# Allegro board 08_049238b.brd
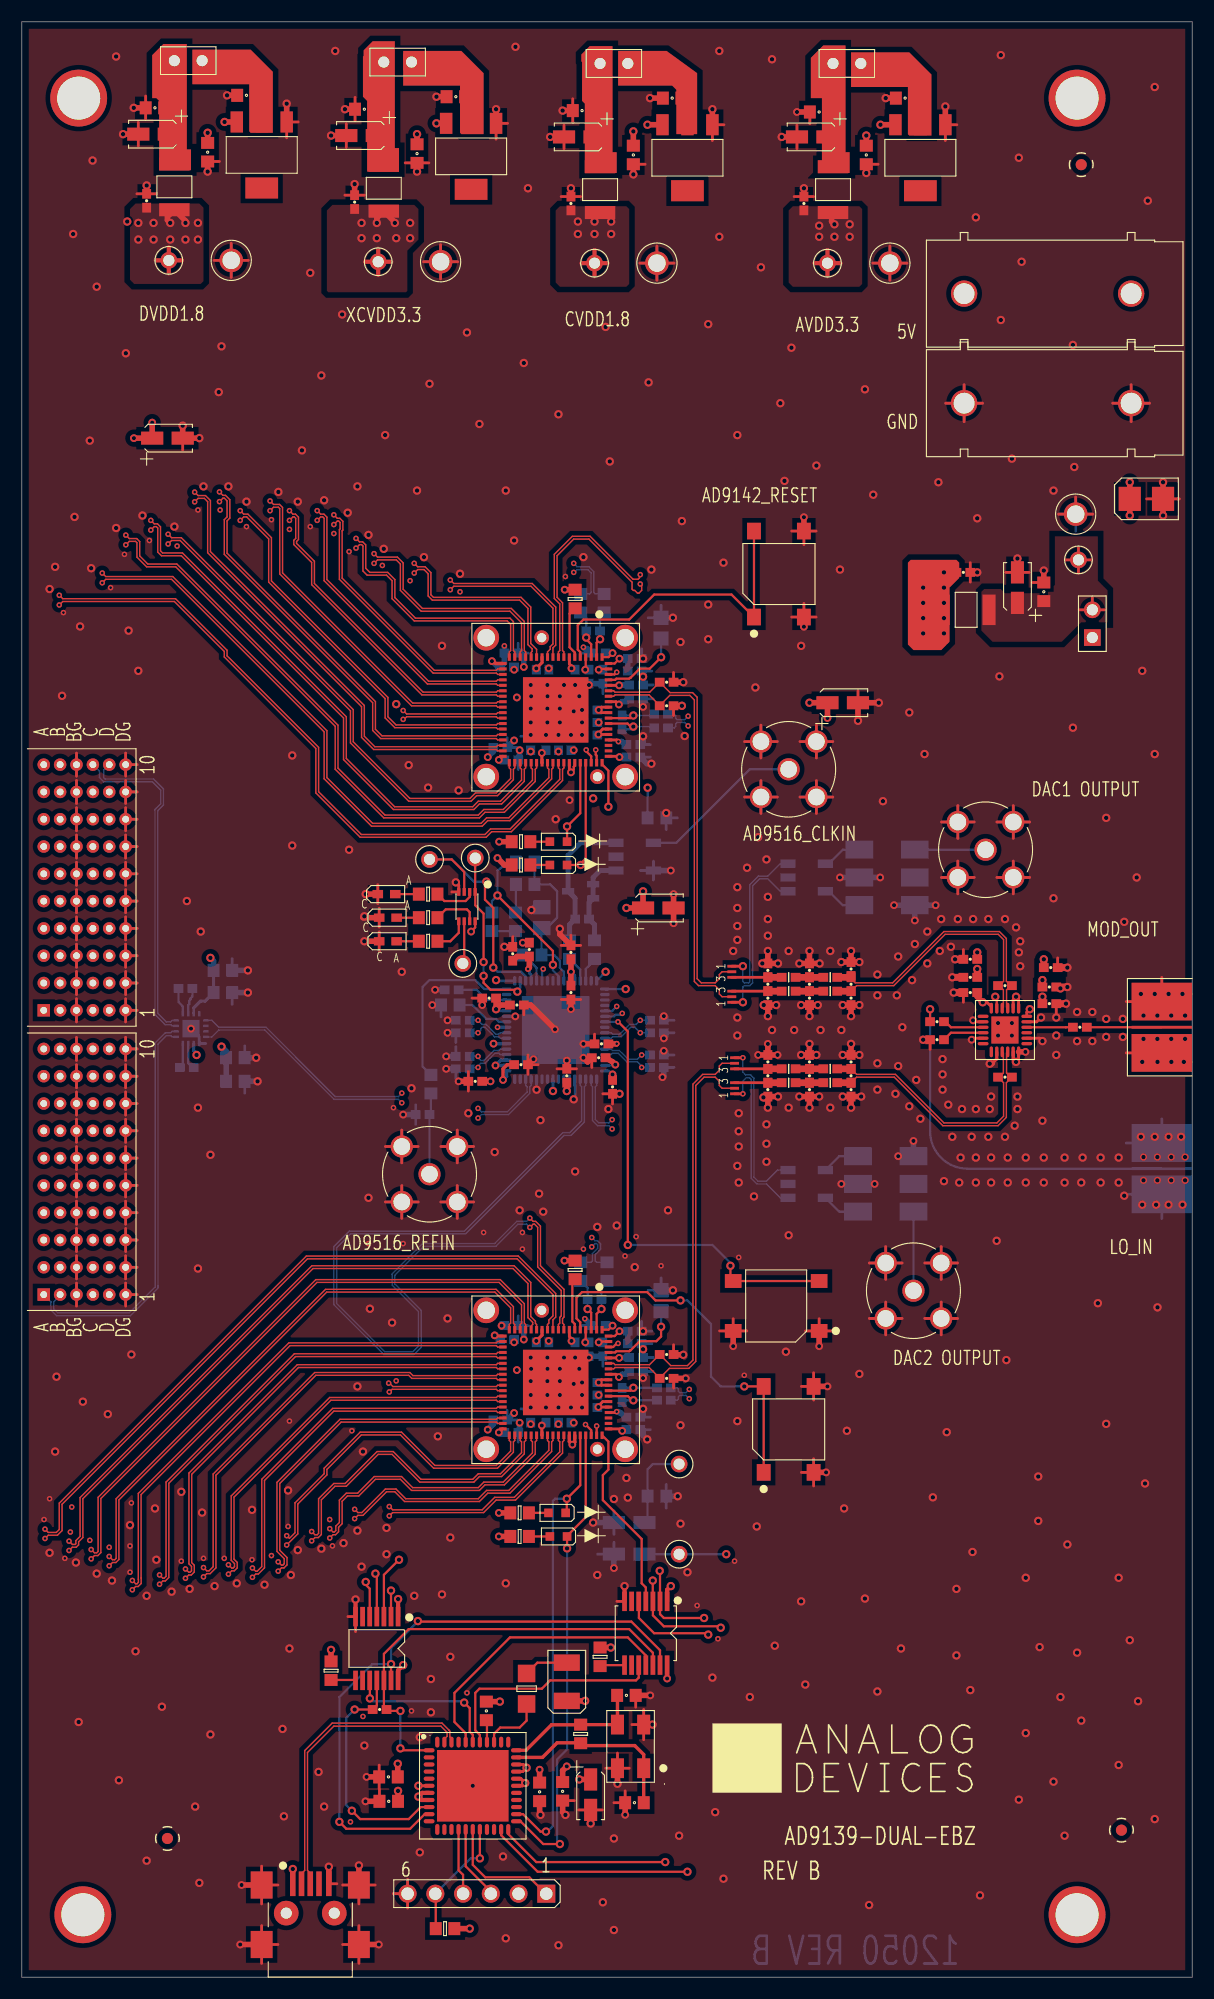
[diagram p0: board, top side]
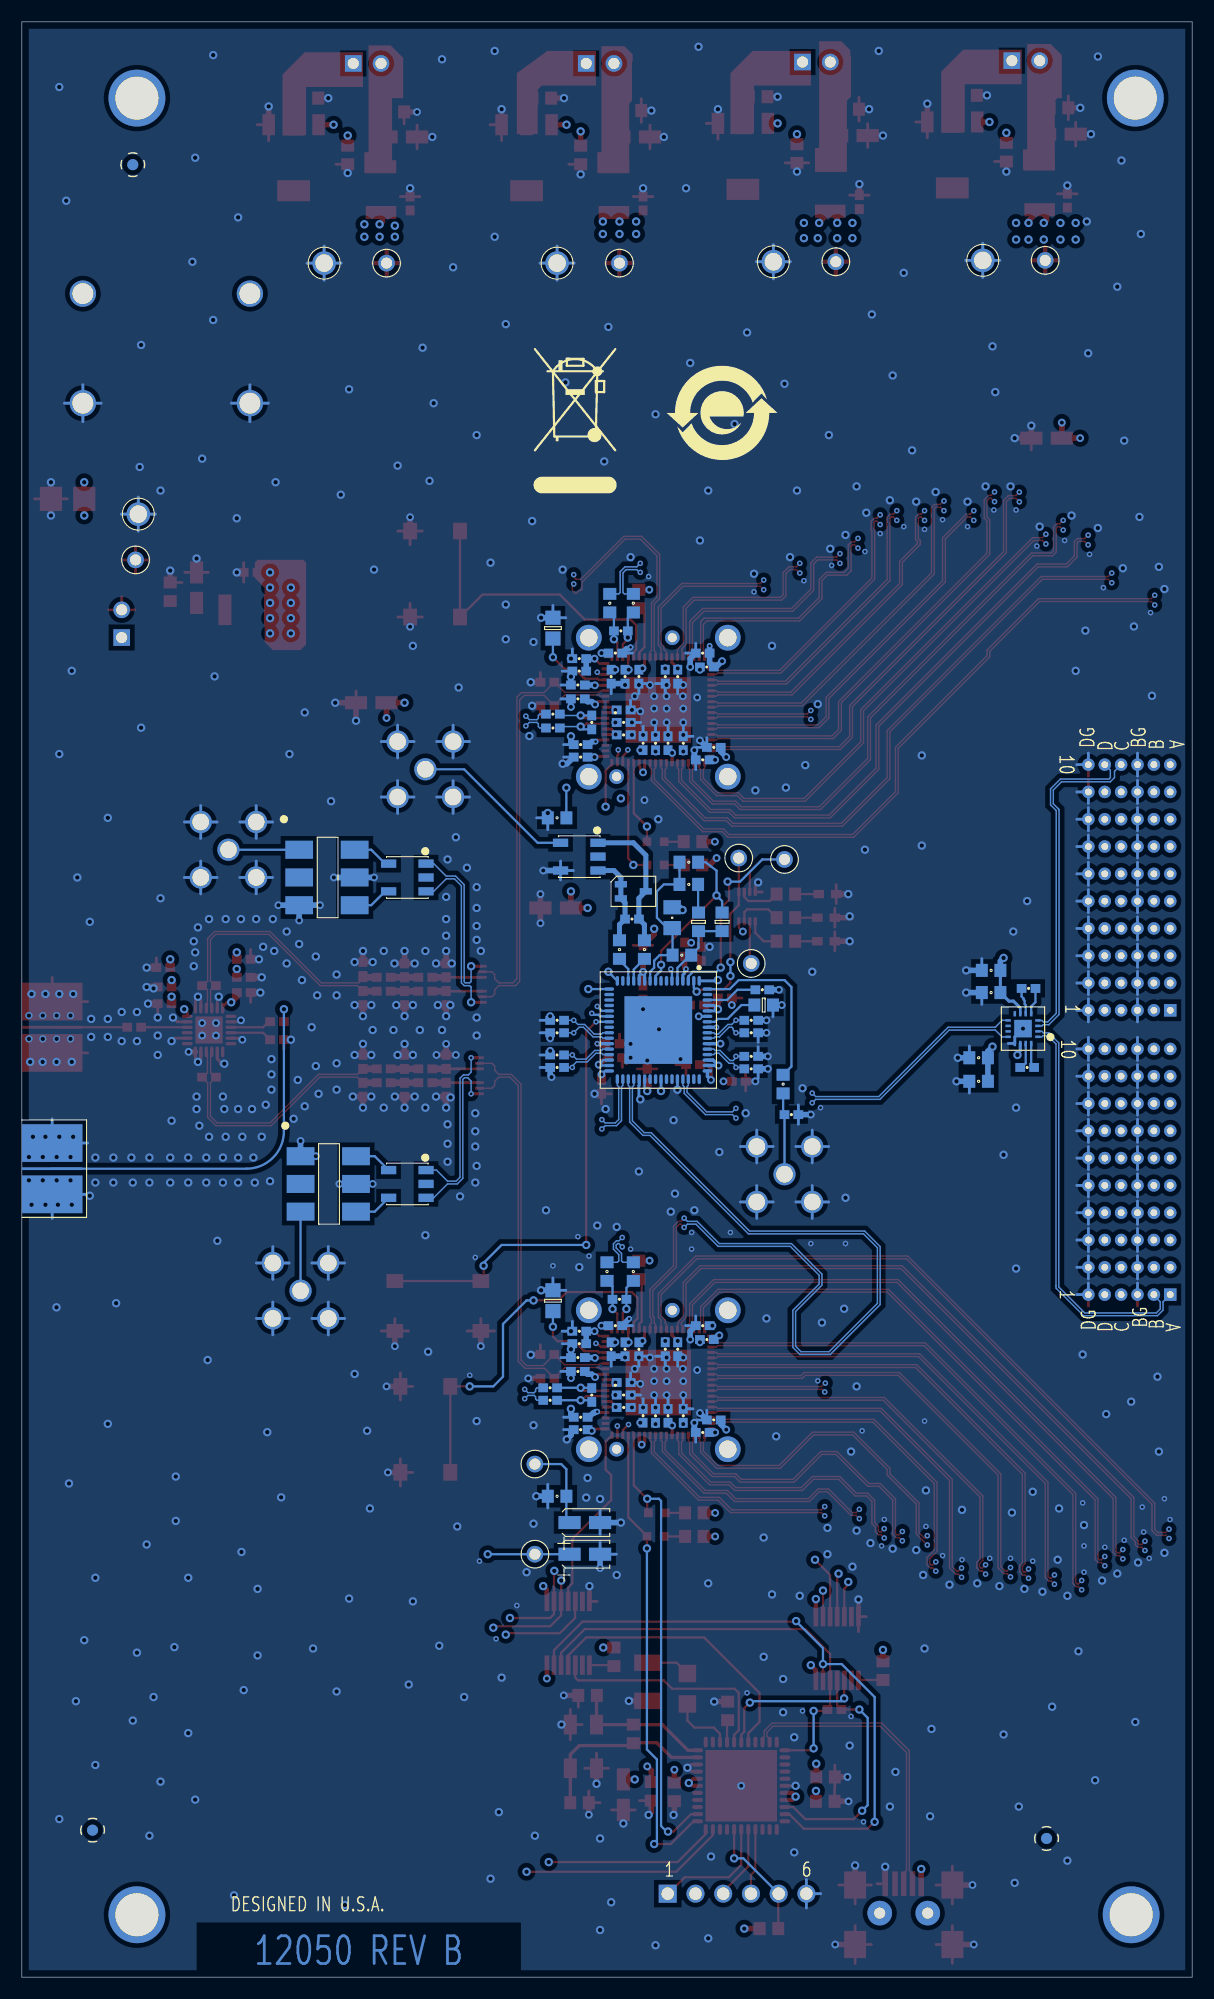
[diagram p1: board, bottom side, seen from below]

Outline 107.19 x 179.07 mm; copper layers: TOP, L2_GND, L3_SIGNAL, L4_GND, L5_PWR, L6_PWR, L7_GND, L8_SIGNAL, L9_GND, BOTTOM. Coordinates in mm from the lower left corner of the outline.
Outline path: 0,179.07 107.19,179.07 107.19,0 0,0 0,179.07

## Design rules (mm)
constraint set DEFAULT: min track width 0.203
net group D0: nets D0_N D0_P
net group D1: nets D1_N D1_P
net group D2: nets D2_N D2_P
net group D2_0: nets D2_0_N D2_0_P
net group D2_1: nets D2_1_N D2_1_P
net group D2_2: nets D2_2_N D2_2_P
net group D2_3: nets D2_3_N D2_3_P
net group D2_4: nets D2_4_N D2_4_P
net group D2_5: nets D2_5_N D2_5_P
net group D2_6: nets D2_6_N D2_6_P
net group D2_7: nets D2_7_N D2_7_P
net group D2_8: nets D2_8_N D2_8_P
net group D2_9: nets D2_9_N D2_9_P
net group D2_10: nets D2_10_N D2_10_P
net group D2_11: nets D2_11_N D2_11_P
net group D2_12: nets D2_12_N D2_12_P
net group D2_13: nets D2_13_N D2_13_P
net group D2_14: nets D2_14_N D2_14_P
net group D2_15: nets D2_15_N D2_15_P
net group D3: nets D3_N D3_P
net group D4: nets D4_N D4_P
net group D5: nets D5_N D5_P
net group D6: nets D6_N D6_P
net group D7: nets D7_N D7_P
net group D8: nets D8_N D8_P
net group D9: nets D9_N D9_P
net group D10: nets D10_N D10_P
net group D11: nets D11_N D11_P
net group D12: nets D12_N D12_P
net group D13: nets D13_N D13_P
net group D14: nets D14_N D14_P
net group D15: nets D15_N D15_P
net group DACCK: nets DACCK_N DACCK_P
net group DACCK2: nets DACCK2_N DACCK2_P
net group DCI: nets DCI1_N DCI1_P
net group DCI2: nets DCI2_N DCI2_P
net group DCO: nets DCO_N DCO_P
net group DP1: nets UNNAMED_12_CAP_I534_N2 UNNAMED_12_CAP_I535_N2
net group DP2: nets UNNAMED_12_NC3PJMPR_I562_A UNNAMED_12_NC3PJMPR_I563_A
net group DP3: nets UNNAMED_12_NC3PJMPR_I562_COM UNNAMED_12_NC3PJMPR_I563_COM
net group DP4: nets UNNAMED_8_NC3PJMPR_I72_A UNNAMED_8_NC3PJMPR_I73_A
net group DP5: nets UNNAMED_8_NC3PJMPR_I72_COM UNNAMED_8_NC3PJMPR_I73_COM
net group DP6: nets UNNAMED_11_CAP_I224_N1 UNNAMED_11_CAP_I226_N1
net group FILT_1: nets FILT_1_N FILT_1_P
net group FILT_2: nets FILT_2_N FILT_2_P
net group FRAME1: nets FRAME1_N FRAME1_P
net group FRAME2: nets FRAME2_N FRAME2_P
net group IBB: nets IBB_N IBB_P
net group Q1: nets Q1_N Q1_P
net group Q2: nets Q2_N Q2_P
net group QBB: nets QBB_N QBB_P
net group REFCK: nets REFCK_N REFCK_P
net group REFCK2: nets REFCK2_N REFCK2_P
net group USB_D: nets USB_D+ USB_D-

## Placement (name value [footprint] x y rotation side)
C1  100UF  [C3528]  103 135.38 0 top
C2  1200PF  [C0603]  46.1 102.11 0 bottom
C3  39000PF  [C0603]  46.1 100.08 0 bottom
C4  2700PF  [C0603]  46.74 93.6 0 bottom
C5  0.1UF  [C0402]  50.29 162.43 90 top
C7  0.1UF  [C0402]  42.8 89.66 180 top
C8  1000PF  [C0402]  83.82 87.5 0 top
C9  0.1UF  [C0402]  46.48 94.11 90 top
C10  0.1UF  [C0402]  44.96 93.73 90 top
C11  0.1UF  [C0402]  53.09 85.47 180 top
C12  0.1UF  [C0402]  50.29 93.85 90 top
C13  0.1UF  [C0402]  50.29 90.17 270 top
C14  0.1UF  [C0402]  52.83 84.2 180 top
C15  0.1UF  [C0402]  54.1 81.53 270 top
C16  0.1UF  [C0402]  49.91 82.55 90 top
C17  0.1UF  [C0402]  45.72 83.57 0 top
C18  0.1UF  [C0603]  50.16 94.11 270 bottom
C19  0.1UF  [C0603]  52.45 94.11 270 bottom
C20  0.1UF  [C0402]  45.34 89.03 0 top
C21  0.1UF  [C0402]  41.53 82.04 180 top
C22  1000PF  [C0402]  83.82 85.85 0 top
C23  1.2PF  [C0402]  68.33 90.93 270 top
C24  .01UF  [C0402]  94.23 92.46 0 top
C25  10000PF  [C0603]  18.41 92.2 0 bottom
C26  .22UF  [C0805]  47.62 97.03 90 bottom
C27  1UF  [C0603]  59.56 172.08 180 top
C28  0.1UF  [C0402]  52.07 113.77 180 bottom
C29  0.1UF  [C0603]  37.47 81.79 90 bottom
C30  1UF  [C0603]  20.57 172.34 180 top
C31  .01UF  [C0402]  86.87 93.22 180 top
C32  1000PF  [C0402]  96.9 87 0 top
C33  1UF  [C0603]  56.01 166.88 270 top
C34  1UF  [C0603]  17.02 167.13 270 top
C35  .1UF  [C0402]  94.11 90.68 0 top
C36  .1UF  [C0402]  86.87 91.57 180 top
C37  1UF  [C0603]  77.34 166.88 270 top
C38  1000PF  [C0402]  94.11 89.15 0 top
C39  0.1UF  [C0402]  71.63 162.43 90 top
C40  1000PF  [C0402]  86.87 90.17 180 top
C42  0.1UF  [C0402]  30.48 162.56 90 top
C43  0.1UF  [C0402]  11.43 162.69 90 top
C44  0.5PF  [C0402]  75.95 90.93 270 top
C46  0.001UF  [C0402]  48.26 57.51 270 bottom
C48  TBD0402  [C0402]  72.14 90.93 270 top
C49  1.2PF  [C0402]  75.95 92.33 270 top
C50  0.1UF  [C0402]  52.07 54.46 180 bottom
C51  10UF  [C3216]  51.05 168.53 180 top
C52  10UF  [C3216]  12.06 168.78 180 top
C53  100PF  [C0402]  52.07 53.31 180 bottom
C54  0.1UF  [C0402]  44.83 49.89 0 bottom
C55  10UF  [C3216]  72.39 168.53 180 top
C56  10UF  [C3216]  31.12 168.66 180 top
C57  0.1UF  [C0603]  51.31 170.94 180 top
C58  0.1UF  [C0603]  12.19 171.2 180 top
C59  0.1UF  [C0402]  49.15 51.41 90 bottom
C60  0.001UF  [C0402]  53.21 57.51 270 bottom
C61  0.1UF  [C0603]  73.03 170.81 180 top
C62  0.1UF  [C0603]  31.37 171.07 180 top
C63  1UF  [C0603]  80.9 172.08 180 top
C64  9PF  [C0402]  72.14 81.28 270 top
C65  TBD0402  [C0402]  68.33 81.28 270 top
C66  0.1UF  [C0603]  18.41 90.17 0 bottom
C67  0.1UF  [C0603]  19.56 84.2 0 bottom
C68  0.001UF  [C0402]  46.61 51.41 90 bottom
C69  0.001UF  [C0402]  44.83 59.66 0 bottom
C70  10000PF  [C0603]  19.56 82.04 0 bottom
C71  100PF  [C0402]  51.94 57.51 270 bottom
C72  100PF  [C0402]  50.67 119.1 270 bottom
C73  100PF  [C0402]  48.01 51.41 90 bottom
C74  TBD0402  [C0402]  68.33 83.82 270 top
C75  9PF  [C0402]  72.14 83.82 270 top
C76  100PF  [C0402]  44.45 58.39 0 bottom
C77  0.1UF  [C0402]  47.12 119.1 270 bottom
C78  0.1UF  [C0402]  56.13 59.16 0 bottom
C79  9PF  [C0402]  72.14 89.66 270 top
C80  TBD0402  [C0402]  68.33 89.66 270 top
C81  TBD0402  [C0402]  68.33 92.2 270 top
C82  9PF  [C0402]  72.14 92.2 270 top
C83  0.1UF  [C0402]  47.12 57.51 270 bottom
C84  0.001UF  [C0402]  56.13 58.01 0 bottom
C85  0.1UF  [C0402]  56.01 111.73 0 bottom
C86  100PF  [C0402]  43.81 51.03 0 bottom
C87  0.001UF  [C0402]  56.26 117.07 0 bottom
C88  100PF  [C0402]  52.83 59.66 180 bottom
C89  100PF  [C0402]  56.26 118.34 0 bottom
C90  100PF  [C0402]  56.01 112.88 0 bottom
C91  0.1UF  [C0603]  58.17 106.17 0 bottom
C92  10UF  [C3216]  75.18 116.71 0 top
C93  1000PF  [C0402]  58.55 115.67 180 bottom
C94  0.1UF  [C0402]  52.07 52.17 180 bottom
C96  1.2PF  [C0402]  75.95 89.66 270 top
C97  1.2PF  [C0402]  68.33 82.55 270 top
C98  TBD0402  [C0402]  72.14 82.55 270 top
C99  1.2PF  [C0402]  75.95 83.82 270 top
C100  0.5PF  [C0402]  75.95 82.55 270 top
C101  1.2PF  [C0402]  75.95 81.28 270 top
C103  0.1UF  [C0603]  53.34 125.83 270 bottom
C104  0.1UF  [C0603]  53.59 64.62 270 bottom
C105  1UF  [C0603]  36.2 167 270 top
C106  100PF  [C0402]  43.81 112.62 0 bottom
C107  0.1UF  [C0603]  51.18 125.83 270 bottom
C108  0.1UF  [C0603]  51.18 64.62 270 bottom
C109  1000PF  [C0402]  58.8 53.98 180 bottom
C110  10UF  [C3216]  13.34 140.94 0 top
C111  1UF  [C0603]  39.75 172.21 180 top
C112  10UF  [C3216]  91.19 127.25 90 top
C113  0.1UF  [C0603]  93.6 126.87 90 top
C114  4.7UF  [C3216]  55.63 38.73 180 bottom
C115  0.1UF  [C0402]  86.23 128.65 0 top
C116  4.7UF  [C3216]  55.63 41.63 180 bottom
C117  0.1UF  [C0402]  44.83 111.48 0 bottom
C118  0.1UF  [C0603]  58.17 44.04 0 bottom
C119  1000PF  [C0402]  58.8 52.83 180 bottom
C120  0.1UF  [C0402]  56.01 50.14 0 bottom
C121  0.1UF  [C0402]  49.15 113 90 bottom
C122  0.001UF  [C0402]  44.83 121.26 0 bottom
C123  100PF  [C0402]  44.45 119.99 0 bottom
C126  100PF  [C0402]  56.01 51.28 0 bottom
C127  0.001UF  [C0402]  56.26 55.47 0 bottom
C128  100PF  [C0402]  56.26 56.74 0 bottom
C133  1000PF  [C0402]  58.55 114.4 180 bottom
C137  0.001UF  [C0402]  53.21 119.1 270 bottom
C139  100PF  [C0402]  51.94 119.1 270 bottom
C140  0.1UF  [C0402]  56.13 120.75 0 bottom
C142  0.001UF  [C0402]  56.13 119.61 0 bottom
C144  100PF  [C0402]  52.83 121.26 180 bottom
C145  100PF  [C0402]  50.29 113 90 bottom
C147  10UF  [C3216]  58.29 97.92 0 top
C148  0.1UF  [C0402]  52.07 116.05 180 bottom
C149  0.001UF  [C0402]  48.26 119.1 270 bottom
C150  0.001UF  [C0402]  46.61 113 90 bottom
C153  100PF  [C0402]  48.01 113 90 bottom
C154  100PF  [C0402]  52.07 114.91 180 bottom
C200  100PF  [C0402]  50.29 51.41 90 bottom
C202  100PF  [C0402]  50.67 57.51 270 bottom
CR3  SML-310MTT86  [LED0603]  33.53 97.03 0 top
CR4  HSMS-281C-BLKG  [SC-70-3]  51.18 99.44 270 bottom
CR5  LG L29K-G2J1-24-Z  [LED0603-2]  49.15 101.85 180 top
CR6  LG L29K-G2J1-24-Z  [LED0603-2]  49.15 103.99 180 top
DS1  SML-310MTT86  [LED0603]  33.4 99.19 0 top
DS2  SML-310MTT86  [LED0603]  33.53 94.87 0 top
DS3  LG L29K-G2J1-24-Z  [LED0603-2]  49.15 40.36 180 top
DS4  LG L29K-G2J1-24-Z  [LED0603-2]  49.02 42.52 180 top
E1  115OHMS  [INDL177W126H71]  52.96 163.7 270 top
E2  115OHMS  [INDL177W126H71]  13.97 163.96 270 top
E5  115OHMS  [INDL177W126H71]  74.3 163.7 270 top
E6  115OHMS  [INDL177W126H71]  33.15 163.83 270 top
E7  115OHMS  [INDL177W126H71]  86.49 125.22 180 top
J1  142-0701-201  [CNJOHNSON142-0701-201]  70.23 110.62 0 top
J2  142-0701-201  [CNJOHNSON142-0701-201]  37.34 73.53 0 top
J3  142-0701-201  [CNJOHNSON142-0701-201]  88.27 103.25 0 top
J4  142-0701-201  [CNJOHNSON142-0701-201]  81.66 62.87 0 top
J6  142-0761-871  [CNSMAL554W250H145]  104.9 87 0 top
J15  142-0761-871  [CNSMAL554W250H145]  104.9 74.04 0 bottom
JP2  69157-102  [CNBERG69157-102]  55.5 175.26 180 top
JP3  69157-102  [CNBERG69157-102]  16.51 175.51 180 top
JP4  3PIN_SOLDER_JUMPER  [JPRSLD03]  65.02 92.08 270 top
JP5  3PIN_SOLDER_JUMPER  [JPRSLD03]  65.02 89.79 90 top
JP6  3PIN_SOLDER_JUMPER  [JPRSLD03]  65.28 81.41 90 top
JP7  3PIN_SOLDER_JUMPER  [JPRSLD03]  65.28 83.69 270 top
JP9  69157-102  [CNBERG69157-102]  76.84 175.26 180 top
JP11  69157-102  [CNBERG69157-102]  35.69 175.39 180 top
JP23  69157-102  [CNBERG69157-102]  98.04 122.68 90 top
L5  12NH  [L0402]  74.04 91.57 0 top
L6  12NH  [L0402]  74.04 90.3 0 top
L7  12NH  [L0402]  74.04 83.19 0 top
L8  12NH  [L0402]  70.23 83.19 0 top
L9  12NH  [L0402]  70.23 81.91 0 top
L10  12NH  [L0402]  70.23 91.57 0 top
L11  12NH  [L0402]  70.23 90.3 0 top
L13  12NH  [L0402]  74.04 81.91 0 top
NOREF  -  []  0 0 0 top
NOREF#2  -  [unnamed#2]  5.21 172.08 0 top
NOREF#3  -  []  113.54 185.42 0 top
NOREF#4  -  []  -248.41 -71.75 0 top
NOREF#5  -  []  107.19 0 90 top
NOREF#6  -  [unnamed#2]  96.65 5.72 0 top
NOREF#7  -  [unnamed#2]  100.71 13.46 0 top
NOREF#8  -  []  0 0 90 top
NOREF#9  -  []  0 0 0 top
NOREF#10  -  []  -6.35 185.42 0 top
NOREF#11  -  [unnamed#2]  96.65 172.08 0 top
NOREF#12  -  []  165.86 -157.73 0 top
NOREF#13  -  []  107.19 179.07 180 top
NOREF#14  -  []  -307.34 -311.91 0 top
NOREF#15  -  []  209.68 189.36 0 top
NOREF#16  -  []  0 0 90 top
NOREF#17  -  []  0 0 0 top
NOREF#18  -  [unnamed#2]  97.03 165.99 0 top
NOREF#19  -  [unnamed#2]  5.59 5.72 0 top
NOREF#20  -  [unnamed#2]  13.34 12.7 0 top
NOREF#21  -  []  54.1 216.66 0 top
NOREF#22  -  []  -6.35 -6.35 0 top
NOREF#23  -  []  0 179.07 270 top
NOREF#24  -  [unnamed#2]  100.71 13.46 180 bottom
NOREF#25  -  []  47.24 152.78 180 bottom
NOREF#26  -  []  62.99 16.89 180 bottom
NOREF#27  -  [unnamed#2]  13.34 12.7 180 bottom
NOREF#28  -  [unnamed#2]  97.03 165.99 180 bottom
NOREF#29  -  []  43.05 143.26 180 bottom
P1  1469028-1  [CNTYCO1469028-1]  2.01 62.51 90 top
P2  1469028-1  [CNTYCO1469028-1]  2.01 88.54 90 top
P5  571-0500  [CNDELTRON-571]  101.6 154.18 180 top
P6  571-0100  [CNDELTRON-571]  101.6 144.14 180 top
R1  226  [R0603]  43.05 96.65 270 bottom
R2  113  [R0603]  45.21 96.65 90 bottom
R3  10K  [R0805]  58.55 61.95 90 bottom
R4  49.9  [R0402]  59.05 118.59 0 top
R5  49.9  [R0402]  59.05 57.02 0 top
R6  49.9  [R0402]  51.31 96.9 0 bottom
R7  200  [R0402]  58.17 86.49 0 bottom
R9  49.9  [R0402]  36.7 78.99 180 bottom
R10  53.6  [R0603]  37.21 99.19 180 top
R11  4.12K  [R0603]  39.24 89.03 0 bottom
R12  5.1K  [R0402]  39.37 90.42 0 bottom
R13  53.6  [R0603]  37.21 94.87 180 top
R14  53.6  [R0603]  37.21 97.03 180 top
R16  1K  [R0603]  45.72 101.85 0 top
R18  49.9  [R0402]  59.05 54.84 0 top
R19  49.9  [R0402]  59.05 116.43 0 top
R20  10K  [R0603]  50.67 64.77 90 top
R21  10K  [R0805]  58.55 123.55 90 bottom
R22  100  [R0402]  52.32 123.29 0 bottom
R23  200  [R0402]  40.39 86.49 180 bottom
R25  1K  [R0603]  45.59 40.36 0 top
R26  0  [R0402]  32.77 24.51 180 top
R27  200  [R0402]  58.17 83.31 0 bottom
R28  200  [R0402]  58.17 84.45 0 bottom
R29  1K  [R0603]  45.59 42.52 0 top
R30  100  [R0402]  14.99 90.55 180 bottom
R31  100  [R0402]  15.11 83.31 180 bottom
R32  200  [R0402]  40.39 83.19 180 bottom
R33  200  [R0402]  40.39 84.33 180 bottom
R38  100  [R0402]  54.99 114.91 270 bottom
R39  1K  [R0603]  45.72 103.99 0 top
R40  10K  [R0603]  50.67 126.21 90 top
R41  100  [R0402]  54.99 53.31 270 bottom
R42  200  [R0402]  58.17 87.63 0 bottom
R43  100  [R0402]  52.45 62.08 0 bottom
R44  200  [R0402]  40.39 87.63 180 bottom
R200  100  [R0402]  90.04 90.81 180 top
R202  100  [R0402]  90.04 82.42 0 top
S1  B3S1000  [SWB3S1000]  69.09 61.47 0 top
S2  B3S1000  [SWB3S1000]  69.34 128.5 270 top
S3  B3S1000  [SWB3S1000]  70.23 50.16 270 top
T1  ETC1-1-13  [ETC1]  71.88 72.64 270 bottom
T2  ETC1-1-13  [ETC1]  56.13 102.62 270 bottom
T3  ADT2-1T-1P+  [MINICD542]  79.12 72.64 270 bottom
T5  ETC1-1-13  [ETC1]  71.88 100.71 270 bottom
T7  ADT2-1T-1P+  [MINICD542]  79.25 100.71 270 bottom
TP1  5000  [CNKEY5001TP]  52.45 156.97 0 top
TP2  5006  [CNKEY5005-9TP]  58.17 156.97 0 top
TP3  5000  [CNKEY5001TP]  13.46 157.23 0 top
TP4  5006  [CNKEY5005-9TP]  19.18 157.23 0 top
TP9  5000  [CNKEY5001TP]  73.79 156.97 0 top
TP10  5006  [CNKEY5005-9TP]  79.5 156.97 0 top
TP11  5000  [CNKEY5001TP]  32.64 157.1 0 top
TP12  5006  [CNKEY5005-9TP]  38.35 157.1 0 top
TP13  5004  [CNKEY5001TP]  40.39 92.84 0 top
TP14  5004  [CNKEY5001TP]  37.34 102.36 0 top
TP15  5004  [CNKEY5001TP]  41.53 102.49 0 top
TP16  5002  [CNKEY5001TP]  60.2 38.73 0 top
TP18  5000  [CNKEY5001TP]  96.77 129.79 270 top
TP19  5006  [CNKEY5005-9TP]  96.52 133.99 270 top
TP20  5002  [CNKEY5001TP]  60.2 46.99 0 top
U1  AD9516-1BCPZ  [QFN64_9X9_PAD6_2X6_2]  48.9 86.74 0 bottom
U3  SY89833LMG  [MLF16_3X3_PAD1_6X1_6]  15.49 86.87 90 bottom
U4  ADL5375-05ACPZ-R7  [QFN24_4X4_PAD2_5X2_5]  90.04 86.74 270 top
U6  ADP3338AKC-1-8  [SOT223-2]  60.96 166.62 180 top
U7  ADP3339AKCZ-1.8-RL  [SOT223-2]  21.97 166.88 180 top
U10  ADP3338AKCZ-3.3  [SOT223-2]  82.3 166.62 180 top
U11  ADP3338AKCZ-3.3  [SOT223-2]  41.15 166.75 180 top
U15  SN74LVC3G34DCUR  [US8]  40.77 98.04 180 top
X1  SG-MLF-7000  [SKTIRONWOOD_MLF72A]  48.9 116.31 180 top
X2  SG-MLF-7000  [SKTIRONWOOD_MLF72A]  48.9 54.71 180 top
XC1  10PF  [C0603]  56.11 15.98 180 top
XC2  10PF  [C0603]  55.37 25.81 0 top
XC3  470PF  [C0603]  42.55 24.38 90 top
XC4  10UF  [C3216]  52.1 16.71 270 top
XC5  0.1UF  [C0603]  47.42 16.97 270 top
XC6  0.1UF  [C0603]  33.58 18.34 180 top
XC7  0.1UF  [C0603]  33.6 16.1 180 top
XC8  0.1UF  [C0603]  49.53 17.02 270 top
XD1  SML-DSP1210USBC-TR (BLUE)  [DIOSML-DSP1210]  49.91 27.05 90 top
XP1  SAMTECTSW10608GS6PIN  [CNBERG1X6H205LD36]  48.03 7.65 180 top
XP2  MUSB-05-F-AB-SM-A-R  [CNSAM-MUSB-05-F-AB-SM-A-R]  26.42 5.72 0 top
XR1  10K  [R0603]  52.96 29.34 270 top
XR2  10K  [R0603]  38.76 4.45 180 top
XR3  1MEG  [R0603]  51.18 22.28 90 top
XR4  150  [R1206]  46.23 26.42 90 top
XR5  10K  [R0603]  28.32 28.07 270 top
XU1  ADG3304BRUZ  [TSSOP14]  57.15 31.5 180 top
XU2  PIC18F4550-I/ML  [QFN44_8X8_PAD6_55X6_55]  41.3 17.53 270 top
XU3  ADG3304BRUZ  [TSSOP14]  32.51 30.1 180 top
XY1  20.000MEGHZ  [XTALABM3B]  55.75 21.13 90 top

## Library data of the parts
C1 = CAPP: User Part Number: UPN; Tolerance: 10; part number: CAPP_SM-100UF,6.3V,10,E000649,C3528; tolerance: 10
C2 = CAP: User Part Number: UPN; Tolerance: 5; alternate symbols: (C0402H22_ALT,C0201-2,C0402_A,C0402_ALT); part number: CAP_SM-1200PF,50V,5,E010128,C0603; tolerance: 5
C3 = CAP: User Part Number: UPN; Tolerance: 10; alternate symbols: (C0402H22_ALT,C0201-2,C0402_A,C0402_ALT); part number: CAP_SM-39000PF,16V,10,E012650,C0603; tolerance: 10
C4 = CAP: User Part Number: UPN; Tolerance: 10; alternate symbols: (C0402H22_ALT,C0201-2,C0402_A,C0402_ALT); part number: CAP_SM-2700PF,50V,10,E010262,C0603; tolerance: 10
C5 C7 C9-C17 C20 C21 C28 C39 C42 C43 C77 C85 C115 C117 C121 C140 C148 = CAP: Tolerance: 10; User Part Number: UPN; alternate symbols: (C0402H22_ALT,C0201-2,C0402_A,C0402_ALT); part number: CAP_SM-0.1UF,16V,10,E007200,C0402; tolerance: 10
C8 C22 C32 C38 C40 = CAP: Tolerance: 10; User Part Number: UPN; alternate symbols: (C0402H22_ALT,C0201-2,C0402_A,C0402_ALT); part number: CAP_SM-1000PF,25V,10,E000257,C0402; tolerance: 10
C18 C19 C29 C58 C61 C66 C67 C91 C103 C104 C107 C108 XC5-XC8 = CAP: User Part Number: UPN; Tolerance: 10; alternate symbols: (C0402H22_ALT,C0201-2,C0402_A,C0402_ALT); part number: CAP_SM-0.1UF,25V,10,E007204,C0603; tolerance: 10
C23 C49 C96 = CAP: Tolerance: +/-0.25PF; User Part Number: UPN; alternate symbols: (C0402H22_ALT,C0201-2,C0402_A,C0402_ALT); part number: CAP_SM-1.2PF,50V,+/-0.25PF,E012428,C0402; tolerance: +/-0.25PF
C24 C31 = CAP: Tolerance: 10; User Part Number: UPN; alternate symbols: (C0402H22_ALT,C0201-2,C0402_A,C0402_ALT); part number: CAP_SM-.01UF,16V,10,E000258,C0402; tolerance: 10
C25 C70 = CAP: User Part Number: UPN; Tolerance: 10; alternate symbols: (C0402H22_ALT,C0201-2,C0402_A,C0402_ALT); part number: CAP_SM-10000PF,50V,10,E000307,C0603; tolerance: 10
C26 = CAP: Tolerance: 10; User Part Number: UPN; alternate symbols: (C0402H22_ALT,C0201-2,C0402_A,C0402_ALT); part number: CAP_SM-.22UF,25V,10,E000220,C0805; tolerance: 10
C27 C33 C105 C111 = CAP: User Part Number: UPN; Tolerance: 10; alternate symbols: (C0402H22_ALT,C0201-2,C0402_A,C0402_ALT); part number: CAP_SM-1UF,16V,10,E006882,C0603; tolerance: 10
C30 C34 C37 C63 = CAP: Tolerance: 10; User Part Number: UPN; alternate symbols: (C0402H22_ALT,C0201-2,C0402_A,C0402_ALT); part number: CAP_SM-1UF,16V,10,E006882,C0603; tolerance: 10
C35 C36 = CAP: Tolerance: 60; User Part Number: UPN; alternate symbols: (C0402H22_ALT,C0201-2,C0402_A,C0402_ALT); part number: CAP_SM-.1UF,16V,60,E000274,C0402; tolerance: 60
C44 = CAP: Tolerance: +/-0.1PF; User Part Number: UPN; alternate symbols: (C0402H22_ALT,C0201-2,C0402_A,C0402_ALT); part number: CAP_SM-0.5PF,50V,+/-0.1PF,E012648,C0402; tolerance: +/-0.1PF
C46 C60 C68 C69 C84 C127 = CAP: User Part Number: UPN; Tolerance: 10; alternate symbols: (C0402H22_ALT,C0201-2,C0402_A,C0402_ALT); part number: CAP_SM-0.001UF,50V,10,E006276,C0402; tolerance: 10
C48 C65 C74 C80 C81 C98 = CAP: User Part Number: UPN; alternate symbols: (C0402H22_ALT,C0201-2,C0402_A,C0402_ALT); part number: CAP_SM-TBD0402,TBD0402,TBD0402,E000381,C0402
C50 C54 C59 C78 C83 C94 C120 = CAP: User Part Number: UPN; Tolerance: 10; alternate symbols: (C0402H22_ALT,C0201-2,C0402_A,C0402_ALT); part number: CAP_SM-0.1UF,16V,10,E007200,C0402; tolerance: 10
C51 C56 C112 = CAPP: User Part Number: UPN; Tolerance: 10; part number: CAPP_SM-10UF,10V,10,E000690,C3216; tolerance: 10
C52 C55 C92 C110 C147 XC4 = CAPP: Tolerance: 10; User Part Number: UPN; part number: CAPP_SM-10UF,10V,10,E000690,C3216; tolerance: 10
C53 C71 C73 C76 C86 C88 C126 C128 C200 C202 = CAP: User Part Number: UPN; Tolerance: 5; alternate symbols: (C0402H22_ALT,C0201-2,C0402_A,C0402_ALT); part number: CAP_SM-100PF,50V,5,E007896,C0402; tolerance: 5
C57 C62 C113 C118 = CAP: Tolerance: 10; User Part Number: UPN; alternate symbols: (C0402H22_ALT,C0201-2,C0402_A,C0402_ALT); part number: CAP_SM-0.1UF,25V,10,E007204,C0603; tolerance: 10
C64 C75 = CAP: User Part Number: UPN; Tolerance: +/-.5PF; alternate symbols: (C0402H22_ALT,C0201-2,C0402_A,C0402_ALT); part number: CAP_SM-9PF,50V,+/-.5PF,E010442,C0402; tolerance: +/-.5PF
C72 C89 C90 C106 C123 C139 C144 C145 C153 C154 = CAP: Tolerance: 5; User Part Number: UPN; alternate symbols: (C0402H22_ALT,C0201-2,C0402_A,C0402_ALT); part number: CAP_SM-100PF,50V,5,E007896,C0402; tolerance: 5
C79 C82 = CAP: Tolerance: +/-.5PF; User Part Number: UPN; alternate symbols: (C0402H22_ALT,C0201-2,C0402_A,C0402_ALT); part number: CAP_SM-9PF,50V,+/-.5PF,E010442,C0402; tolerance: +/-.5PF
C87 C122 C137 C142 C149 C150 = CAP: Tolerance: 10; User Part Number: UPN; alternate symbols: (C0402H22_ALT,C0201-2,C0402_A,C0402_ALT); part number: CAP_SM-0.001UF,50V,10,E006276,C0402; tolerance: 10
C93 C133 = CAP: Tolerance: 5; User Part Number: UPN; alternate symbols: (C0402H22_ALT,C0201-2,C0402_A,C0402_ALT); part number: CAP_SM-1000PF,50V,5,E012419,C0402; tolerance: 5
C97 C99 C101 = CAP: User Part Number: UPN; Tolerance: +/-0.25PF; alternate symbols: (C0402H22_ALT,C0201-2,C0402_A,C0402_ALT); part number: CAP_SM-1.2PF,50V,+/-0.25PF,E012428,C0402; tolerance: +/-0.25PF
C100 = CAP: User Part Number: UPN; Tolerance: +/-0.1PF; alternate symbols: (C0402H22_ALT,C0201-2,C0402_A,C0402_ALT); part number: CAP_SM-0.5PF,50V,+/-0.1PF,E012648,C0402; tolerance: +/-0.1PF
C109 C119 = CAP: User Part Number: UPN; Tolerance: 5; alternate symbols: (C0402H22_ALT,C0201-2,C0402_A,C0402_ALT); part number: CAP_SM-1000PF,50V,5,E012419,C0402; tolerance: 5
C114 = CAPP: Tolerance: 10; User Part Number: UPN; part number: CAPP_SM-4.7UF,20V,10,E000691,C3216; tolerance: 10
C116 = CAPP: User Part Number: UPN; Tolerance: 10; part number: CAPP_SM-4.7UF,20V,10,E000691,C3216; tolerance: 10
CR3 DS1 DS2 = DIOLED: Tolerance: N/A; User Part Number: UPN; part number: DIOLED_SM-SML-310MTT86,2.8V,N/A,E001179,LED0603; tolerance: N/A
CR4 = DIOHSMS28X2: Tolerance: N/A; User Part Number: UPN; part number: DIOHSMS28X2_SM-HSMS-281C-BLKG,0.4V,N/A,E007526,SC-70-3; tolerance: N/A
CR5 CR6 = DIOLED: Tolerance: N/A; User Part Number: UPN; part number: DIOLED_SM-LG L29K-G2J1-24-Z,1.7V,N/A,E010948,LED0603-2; tolerance: N/A
DS3 DS4 = DIOLED: User Part Number: UPN; Tolerance: N/A; part number: DIOLED_SM-LG L29K-G2J1-24-Z,1.7V,N/A,E010948,LED0603-2; tolerance: N/A
E1 E6 E7 = FERRITE: User Part Number: UPN; Tolerance: N/A; part number: FERRITE_SM-115OHMS,N/A,E006418,INDL177W126H71; tolerance: N/A
E2 E5 = FERRITE: Tolerance: N/A; User Part Number: UPN; part number: FERRITE_SM-115OHMS,N/A,E006418,INDL177W126H71; tolerance: N/A
J1-J4 = CNBNC5P: User Part Number: UPN; alternate symbols: (CNAMPHENOL132255-11_ALT); part number: CNBNC5P_TH-142-0701-201,E000916,JOHNSON,142-0701-201,SCD-013999,CNJOHNSON142-0701-201
J6 J15 = CNBNC3P: User Part Number: UPN; part number: CNBNC3P_SM-142-0761-871,E016260,EMERSON NETWORK POWER,142-0761-871,SCD-003060,CNSMAL554W250H145
JP2 JP3 JP9 JP11 JP23 = CNJMPRSHRT: User Part Number: UPN; part number: CNJMPRSHRT_TH-69157-102,E000942,CNBERG69157-102
JP4-JP7 = NC3P_JMPR: User Part Number: UPN; part number: NC3P_JMPR_SM-3PIN_SOLDER_JUMPER,E005606,JPRSLD03
L5-L11 L13 = IND: Tolerance: 2; User Part Number: UPN; alternate symbols: (L0402-2,L0603_ALT); part number: IND_SM-12NH,2,E008056,L0402; tolerance: 2
P1 P2 = CNTYCO60P: User Part Number: UPN; part number: CNTYCO60P_TH-1469028-1,E006333,CNTYCO1469028-1
P5 = CN2P: User Part Number: UPN; part number: CN2P_TH-571-0500,E007692,DELTRON,571-0500,SCD-003573,CNDELTRON-571
P6 = CN2P: User Part Number: UPN; part number: CN2P_TH-571-0100,E007691,DELTRON,571-0100,SCD-003573,CNDELTRON-571
R1 = RES: Tolerance: 1; User Part Number: UPN; alternate symbols: (RRAD984L1500W75H520LD32;TO220H590_ALT;R0402_A;R0603_A); part number: RES_SM-226,E010255,1/10W,1,PANASONIC,ERJ-3EKF2260V,SCD-001006,R0603,N/A; tolerance: 1
R2 = RES: Tolerance: 1; User Part Number: UPN; alternate symbols: (RRAD984L1500W75H520LD32;TO220H590_ALT;R0402_A;R0603_A); part number: RES_SM-113,E006791,1/10W,1,PANASONIC,ERJ-3EKF1130V,SCD-001006,R0603,N/A; tolerance: 1
R3 = RES: User Part Number: UPN; Tolerance: 0.1; alternate symbols: (RRAD984L1500W75H520LD32;TO220H590_ALT;R0402_A;R0603_A); part number: RES_SM-10K,E003806,1/8W,0.1,PANASONIC,ERA-6YEB103V,SCD-001690,R0805,N/A; tolerance: 0.1
R4 R5 R9 R18 R19 = RES: Tolerance: 0.1; User Part Number: UPN; alternate symbols: (RRAD984L1500W75H520LD32;TO220H590_ALT;R0402_A;R0603_A); part number: RES_SM-49.9,E005976,1/16W,0.1,SUSUMU,RG1005P-49R9-B-T5,SCD-002134,R0402,N/A; tolerance: 0.1
R6 = RES: Tolerance: 1; User Part Number: UPN; alternate symbols: (RRAD984L1500W75H520LD32;TO220H590_ALT;R0402_A;R0603_A); part number: RES_SM-49.9,E003750,1/16W,1,PANASONIC,ERJ-2RKF49R9X,SCD-001006,R0402,N/A; tolerance: 1
R7 R23 R27 R28 R32 R33 R42 R44 = RES: Tolerance: 1; User Part Number: UPN; alternate symbols: (RRAD984L1500W75H520LD32;TO220H590_ALT;R0402_A;R0603_A); part number: RES_SM-200,E003753,1/16W,1,PANASONIC,ERJ-2RKF2000X,SCD-001006,R0402,N/A; tolerance: 1
R10 R13 R14 = RES: Tolerance: 1; User Part Number: UPN; alternate symbols: (RRAD984L1500W75H520LD32;TO220H590_ALT;R0402_A;R0603_A); part number: RES_SM-53.6,E003689,1/10W,1,PANASONIC,ERJ-3EKF53R6V,SCD-001006,R0603,N/A; tolerance: 1
R11 = RES: Tolerance: 0.1; User Part Number: UPN; alternate symbols: (RRAD984L1500W75H520LD32;TO220H590_ALT;R0402_A;R0603_A); part number: RES_SM-4.12K,E010300,1/16W,0.1,SUSUMU,RR0816P-4121-B-T5-60H,SCD-012125,R0603,N/A; tolerance: 0.1
R12 = RES: Tolerance: 0.1; User Part Number: UPN; alternate symbols: (RRAD984L1500W75H520LD32;TO220H590_ALT;R0402_A;R0603_A); part number: RES_SM-5.1K,E010267,1/16W,0.1,PANASONIC,ERA-2AEB512X,SCD-012103,R0402,N/A; tolerance: 0.1
R16 R39 = RES: Tolerance: 1; User Part Number: UPN; alternate symbols: (RRAD984L1500W75H520LD32;TO220H590_ALT;R0402_A;R0603_A); part number: RES_SM-1K,E003678,1/10W,1,PANASONIC,ERJ-3EKF1001V,SCD-001006,R0603,N/A; tolerance: 1
R20 R40 XR1 XR2 XR5 = RES: Tolerance: 1; User Part Number: UPN; alternate symbols: (RRAD984L1500W75H520LD32;TO220H590_ALT;R0402_A;R0603_A); part number: RES_SM-10K,E003671,1/10W,1,PANASONIC,ERJ-3EKF1002V,SCD-001006,R0603,N/A; tolerance: 1
R21 = RES: Tolerance: 0.1; User Part Number: UPN; alternate symbols: (RRAD984L1500W75H520LD32;TO220H590_ALT;R0402_A;R0603_A); part number: RES_SM-10K,E003806,1/8W,0.1,PANASONIC,ERA-6YEB103V,SCD-001690,R0805,N/A; tolerance: 0.1
R22 R30 R31 R38 R41 R43 R200 R202 = RES: Tolerance: 1; User Part Number: UPN; alternate symbols: (RRAD984L1500W75H520LD32;TO220H590_ALT;R0402_A;R0603_A); part number: RES_SM-100,E003760,1/16W,1,VENKEL,CR0402-16W-1000FPT,NONE,R0402,N/A; tolerance: 1
R25 R29 = RES: User Part Number: UPN; Tolerance: 1; alternate symbols: (RRAD984L1500W75H520LD32;TO220H590_ALT;R0402_A;R0603_A); part number: RES_SM-1K,E003678,1/10W,1,PANASONIC,ERJ-3EKF1001V,SCD-001006,R0603,N/A; tolerance: 1
R26 = RES: Tolerance: 5; User Part Number: UPN; alternate symbols: (RRAD984L1500W75H520LD32;TO220H590_ALT;R0402_A;R0603_A); part number: RES_SM-0,E003438,1/16W,5,PANASONIC,ERJ-2GE0R00X,SCD-002744,R0402,N/A; tolerance: 5
S1-S3 = SWSPST4PIN: User Part Number: UPN; part number: SWSPST4PIN_SM-B3S1000,E004572,SWB3S1000
T1 T5 = XFMRETC1: User Part Number: UPN; part number: XFMRETC1_SM-ETC1-1-13,E004586,ETC1
T2 = XFMRETC1_5P: User Part Number: UPN; part number: XFMRETC1_5P_SM-ETC1-1-13,E004586,ETC1
T3 T7 = XFMRMCCD542KS: User Part Number: UPN; part number: XFMRMCCD542KS_SM-ADT2-1T-1P+,E007172,MINICD542
TP1 TP3 TP9 TP11 TP18 = CNTP1P: User Part Number: UPN; alternate symbols: (CNBANANA_ALT); part number: CNTP1P_TH-5000,E016323,CNKEY5001TP
TP2 TP4 TP10 TP12 TP19 = CNTP1P: User Part Number: UPN; alternate symbols: (CNBANANA_ALT); part number: CNTP1P_TH-5006,E015367,CNKEY5005-9TP
TP13-TP15 = CNTP1P: User Part Number: UPN; alternate symbols: (CNBANANA_ALT); part number: CNTP1P_TH-5004,E016321,CNKEY5001TP
TP16 TP20 = CNTP1P: User Part Number: UPN; alternate symbols: (CNBANANA_ALT); part number: CNTP1P_TH-5002,E006153,CNKEY5001TP
U1 = AD9516: User Part Number: UPN; part number: AD9516_SM-AD9516-1BCPZ,E007638,QFN64_9X9_PAD6_2X6_2,N/A
U3 = ICSY89833: User Part Number: UPN; part number: ICSY89833_SM-SY89833LMG,E007967,MLF16_3X3_PAD1_6X1_6
U4 = ADL5375: User Part Number: UPN; part number: ADL5375_SM-ADL5375-05ACPZ-R7,E007336,QFN24_4X4_PAD2_5X2_5,N/A
U6 = ADP3338: User Part Number: UPN; part number: ADP3338_SM-ADP3338AKC-1-8,E004720,SOT223-2,N/A
U7 = ADP3338: User Part Number: UPN; part number: ADP3338_SM-ADP3339AKCZ-1.8-RL,E006248,SOT223-2,N/A
U10 U11 = ADP3338: User Part Number: UPN; part number: ADP3338_SM-ADP3338AKCZ-3.3,E004961,SOT223-2,N/A
U15 = SN74LVC3G34: User Part Number: UPN; part number: SN74LVC3G34_SM-SN74LVC3G34DCUR,E005887,US8
X1 X2 = SKTQFN72_PAD: User Part Number: UPN; part number: SKTQFN72_PAD_SM-SG-MLF-7000,E007305,SKTIRONWOOD_MLF72A
XC1 XC2 = CAP: User Part Number: UPN; Tolerance: 5; alternate symbols: (C0402H22_ALT,C0201-2,C0402_A,C0402_ALT); part number: CAP_SM-10PF,50V,5,E010138,C0603; tolerance: 5
XC3 = CAP: User Part Number: UPN; Tolerance: 5; alternate symbols: (C0402H22_ALT,C0201-2,C0402_A,C0402_ALT); part number: CAP_SM-470PF,50V,5,E010115,C0603; tolerance: 5
XD1 = DIOLED: Tolerance: N/A; User Part Number: UPN; part number: DIOLED_SM-SML-DSP1210USBC-TR (BLUE),1.5V,N/A,E006227,DIOSML-DSP1210; tolerance: N/A
XP1 = CN6P: User Part Number: UPN; part number: CN6P_TH-SAMTECTSW10608GS6PIN,E000872,CNBERG1X6H205LD36
XP2 = CN5P_4PSHLD_A: User Part Number: UPN; part number: CN5P_4PSHLD_A_TH-MUSB-05-F-AB-SM-A-R,E006666,CNSAM-MUSB-05-F-AB-SM-A-R
XR3 = RES: Tolerance: 1; User Part Number: UPN; alternate symbols: (RRAD984L1500W75H520LD32;TO220H590_ALT;R0402_A;R0603_A); part number: RES_SM-1MEG,E003682,1/10W,1,PANASONIC,ERJ-3EKF1004V,SCD-001006,R0603,N/A; tolerance: 1
XR4 = RES: Tolerance: 1; User Part Number: UPN; alternate symbols: (RRAD984L1500W75H520LD32;TO220H590_ALT;R0402_A;R0603_A); part number: RES_SM-150,E003233,1/4W,1,PANASONIC,ERJ-8ENF1500V,SCD-001006,R1206,N/A; tolerance: 1
XU1 XU3 = ADG3304: User Part Number: UPN; part number: ADG3304_SM-ADG3304BRUZ,E007035,TSSOP14,N/A
XU2 = ICPIC18F4550: User Part Number: UPN; part number: ICPIC18F4550_SM-PIC18F4550-I/ML,E007514,QFN44_8X8_PAD6_55X6_55
XY1 = XTALACABM8: User Part Number: UPN; part number: XTALACABM8_SM-20.000MEGHZ,E007421,XTALABM3B

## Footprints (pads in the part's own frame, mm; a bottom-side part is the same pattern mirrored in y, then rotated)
C0402
  rect 0.889x0.813 smd: 1(-0.635,0) 2(0.635,0)
C0603
  rect 1.092x1.194 smd: 1(-0.851,0) 2(0.851,0)
C0805
  rect 1.295x1.6 smd: 1(-0.953,0) 2(0.953,0)
C3216
  rect 2.032x1.194 smd: N(1.397,0) P(-1.397,0)
C3528
  rect 2.032x2.21 smd: N(1.524,0) P(-1.524,0)
CNBERG1X6H205LD36
  rect 1.651x1.651 hole 1.143: 1(0,0)
  round 1.651 hole 1.143: 2(2.54,0) 3(5.08,0) 4(7.62,0) 5(10.16,0) 6(12.7,0)
CNBERG69157-102
  rect 1.524x1.524 hole 1.016: 1(0,0)
  round 1.524 hole 1.016: 2(2.54,0)
CNDELTRON-571
  round 2.413 hole 1.905: 1(0,0) 2(15.3,0)
CNJOHNSON142-0701-201
  round 2.032 hole 1.524: 1(0,0) 2(-2.54,2.54) 3(2.54,2.54) 4(2.54,-2.54) 5(-2.54,-2.54)
CNKEY5001TP
  round 1.524 hole 1.016: 1(0,0)
CNKEY5005-9TP
  round 2.159 hole 1.6: 1(0,0)
CNSAM-MUSB-05-F-AB-SM-A-R
  round 2.261 hole 1.016 unplated: (-2.2,0.15) (2.2,0.15)
  rect 0.508x2.261 smd: 1(-1.6,2.839) 2(-0.8,2.839) 3(0,2.839) 4(0.8,2.839) 5(1.7,2.839)
  rect 2.007x2.489 smd: PAD1(-4.453,2.725) PAD2(4.453,2.725) PAD3(4.453,-2.725) PAD4(-4.453,-2.725)
CNSMAL554W250H145
  rect 5.537x0.254 smd: 1(-0.495,0)
  rect 5.537x3.454 smd: 2(-0.495,2.349) 3(-0.495,-2.349)
CNTYCO1469028-1
  rect 1.143x1.143 hole 0.635: A1(0,0)
  round 1.143 hole 0.635: A2(2.5,0) A3(5,0) A4(7.5,0) A5(10,0) A6(12.5,0) A7(15,0) A8(17.5,0) A9(20,0) A10(22.5,0) B1(0,-1.5) B2(2.5,-1.5) B3(5,-1.5) B4(7.5,-1.5) B5(10,-1.5) B6(12.5,-1.5) B7(15,-1.5) B8(17.5,-1.5) B9(20,-1.5) B10(22.5,-1.5) BG1(0,-3) BG2(2.5,-3) BG3(5,-3) BG4(7.5,-3) BG5(10,-3) BG6(12.5,-3) BG7(15,-3) BG8(17.5,-3) BG9(20,-3) BG10(22.5,-3) C1(0,-4.5) C2(2.5,-4.5) C3(5,-4.5) C4(7.5,-4.5) C5(10,-4.5) C6(12.5,-4.5) C7(15,-4.5) C8(17.5,-4.5) C9(20,-4.5) C10(22.5,-4.5) D1(0,-6) D2(2.5,-6) D3(5,-6) D4(7.5,-6) D5(10,-6) D6(12.5,-6) D7(15,-6) D8(17.5,-6) D9(20,-6) D10(22.5,-6) DG1(0,-7.5) DG2(2.5,-7.5) DG3(5,-7.5) DG4(7.5,-7.5) DG5(10,-7.5) DG6(12.5,-7.5) DG7(15,-7.5) DG8(17.5,-7.5) DG9(20,-7.5) DG10(22.5,-7.5)
DIOSML-DSP1210
  rect 1.499x2.388 smd: A(1.75,0) C(-1.75,0)
ETC1
  rect 0.762x1.397 smd: 1(-1.27,1.714) 2(0,1.714) 3(1.27,1.714) 4(1.27,-1.714) 5(-1.27,-1.714)
INDL177W126H71
  rect 1.194x2.794 smd: 1(-2.097,0) 2(2.097,0)
JPRSLD03
  rect 0.254x0.813 smd: 1(-0.508,0) 2(0,0) 3(0.508,0)
L0402
  rect 0.889x0.813 smd: 1(-0.635,0) 2(0.635,0)
LED0603
  rect 0.965x0.762 smd: A(0.8,0) C(-0.8,0)
LED0603-2
  rect 0.787x0.787 smd: A(0.787,0) C(-0.787,0)
MINICD542
  rect 1.651x2.54 smd: 1(-2.54,-2.54) 2(0,-2.54) 3(2.54,-2.54) 4(2.54,2.54) 5(0,2.54) 6(-2.54,2.54)
MLF16_3X3_PAD1_6X1_6
  rect 0.229x0.483 smd: 1(-0.75,-1.361) 2(-0.25,-1.361) 3(0.25,-1.361) 4(0.75,-1.361) 9(0.75,1.361) 10(0.25,1.361) 11(-0.25,1.361) 12(-0.75,1.361)
  rect 0.483x0.229 smd: 5(1.361,-0.75) 6(1.361,-0.25) 7(1.361,0.25) 8(1.361,0.75) 13(-1.361,0.75) 14(-1.361,0.25) 15(-1.361,-0.25) 16(-1.361,-0.75)
  rect 1.6x1.6 smd: PAD(0,0)
QFN24_4X4_PAD2_5X2_5
  oval 0.305x0.991 smd: 1(-1.25,-2) 2(-0.75,-2) 3(-0.25,-2) 4(0.25,-2) 5(0.75,-2) 6(1.25,-2) 13(1.25,2) 14(0.75,2) 15(0.25,2) 16(-0.25,2) 17(-0.75,2) 18(-1.25,2)
  oval 0.991x0.305 smd: 7(2,-1.25) 8(2,-0.75) 9(2,-0.25) 10(2,0.25) 11(2,0.75) 12(2,1.25) 19(-2,1.25) 20(-2,0.75) 21(-2,0.25) 22(-2,-0.25) 23(-2,-0.75) 24(-2,-1.25)
  rect 2.489x2.489 smd: PAD(0,0)
QFN44_8X8_PAD6_55X6_55
  oval 0.381x0.991 smd: 1(-3.25,-4) 2(-2.6,-4) 3(-1.95,-4) 4(-1.3,-4) 5(-0.65,-4) 6(0,-4) 7(0.65,-4) 8(1.3,-4) 9(1.95,-4) 10(2.6,-4) 11(3.25,-4) 23(3.25,4) 24(2.6,4) 25(1.95,4) 26(1.3,4) 27(0.65,4) 28(0,4) 29(-0.65,4) 30(-1.3,4) 31(-1.95,4) 32(-2.6,4) 33(-3.25,4)
  oval 0.991x0.381 smd: 12(4,-3.25) 13(4,-2.6) 14(4,-1.95) 15(4,-1.3) 16(4,-0.65) 17(4,0) 18(4,0.65) 19(4,1.3) 20(4,1.95) 21(4,2.6) 22(4,3.25) 34(-4,3.25) 35(-4,2.6) 36(-4,1.95) 37(-4,1.3) 38(-4,0.65) 39(-4,0) 40(-4,-0.65) 41(-4,-1.3) 42(-4,-1.95) 43(-4,-2.6) 44(-4,-3.25)
  rect 6.553x6.553 smd: PAD(0,0)
QFN64_9X9_PAD6_2X6_2
  oval 0.305x0.889 smd: 1(-3.75,-4.5) 2(-3.25,-4.5) 3(-2.75,-4.5) 4(-2.25,-4.5) 5(-1.75,-4.5) 6(-1.25,-4.5) 7(-0.75,-4.5) 8(-0.25,-4.5) 9(0.25,-4.5) 10(0.75,-4.5) 11(1.25,-4.5) 12(1.75,-4.5) 13(2.25,-4.5) 14(2.75,-4.5) 15(3.25,-4.5) 16(3.75,-4.5) 33(3.75,4.5) 34(3.25,4.5) 35(2.75,4.5) 36(2.25,4.5) 37(1.75,4.5) 38(1.25,4.5) 39(0.75,4.5) 40(0.25,4.5) 41(-0.25,4.5) 42(-0.75,4.5) 43(-1.25,4.5) 44(-1.75,4.5) 45(-2.25,4.5) 46(-2.75,4.5) 47(-3.25,4.5) 48(-3.75,4.5)
  oval 0.889x0.305 smd: 17(4.5,-3.75) 18(4.5,-3.25) 19(4.5,-2.75) 20(4.5,-2.25) 21(4.5,-1.75) 22(4.5,-1.25) 23(4.5,-0.75) 24(4.5,-0.25) 25(4.5,0.25) 26(4.5,0.75) 27(4.5,1.25) 28(4.5,1.75) 29(4.5,2.25) 30(4.5,2.75) 31(4.5,3.25) 32(4.5,3.75) 49(-4.5,3.75) 50(-4.5,3.25) 51(-4.5,2.75) 52(-4.5,2.25) 53(-4.5,1.75) 54(-4.5,1.25) 55(-4.5,0.75) 56(-4.5,0.25) 57(-4.5,-0.25) 58(-4.5,-0.75) 59(-4.5,-1.25) 60(-4.5,-1.75) 61(-4.5,-2.25) 62(-4.5,-2.75) 63(-4.5,-3.25) 64(-4.5,-3.75)
  rect 6.198x6.198 smd: PAD(0,0)
R0402
  rect 0.889x0.813 smd: 1(-0.635,0) 2(0.635,0)
R0603
  rect 1.092x1.194 smd: 1(-0.851,0) 2(0.851,0)
R0805
  rect 1.295x1.397 smd: 1(-0.953,0) 2(0.953,0)
R1206
  rect 1.6x1.6 smd: 1(-1.397,0) 2(1.397,0)
SC-70-3
  rect 0.584x1.118 smd: 1(-0.65,-1.144) 2(0.65,-1.144) 3(0,1.144)
SKTIRONWOOD_MLF72A
  round 2.362 hole 1.6 unplated: (-6.362,6.362) (-6.362,-6.362) (6.362,6.362) (6.362,-6.362)
  round 1.346 hole 0.838 unplated: (-3.822,6.362) (1.282,-6.362)
  rect 0.279x0.686 smd: 1(-4.25,-4.587) 2(-3.75,-4.587) 3(-3.25,-4.587) 4(-2.75,-4.587) 5(-2.25,-4.587) 6(-1.75,-4.587) 7(-1.25,-4.587) 8(-0.75,-4.587) 9(-0.25,-4.587) 10(0.25,-4.587) 11(0.75,-4.587) 12(1.25,-4.587) 13(1.75,-4.587) 14(2.25,-4.587) 15(2.75,-4.587) 16(3.25,-4.587) 17(3.75,-4.587) 18(4.25,-4.587) 37(4.25,5.087) 38(3.75,5.087) 39(3.25,5.087) 40(2.75,5.087) 41(2.25,5.087) 42(1.75,5.087) 43(1.25,5.087) 44(0.75,5.087) 45(0.25,5.087) 46(-0.25,5.087) 47(-0.75,5.087) 48(-1.25,5.087) 49(-1.75,5.087) 50(-2.25,5.087) 51(-2.75,5.087) 52(-3.25,5.087) 53(-3.75,5.087) 54(-4.25,5.087)
  rect 0.686x0.279 smd: 19(4.837,-4) 20(4.837,-3.5) 21(4.837,-3) 22(4.837,-2.5) 23(4.837,-2) 24(4.837,-1.5) 25(4.837,-1) 26(4.837,-0.5) 27(4.837,0) 28(4.837,0.5) 29(4.837,1) 30(4.837,1.5) 31(4.837,2) 32(4.837,2.5) 33(4.837,3) 34(4.837,3.5) 35(4.837,4) 36(4.837,4.5) 55(-4.837,4.5) 56(-4.837,4) 57(-4.837,3.5) 58(-4.837,3) 59(-4.837,2.5) 60(-4.837,2) 61(-4.837,1.5) 62(-4.837,1) 63(-4.837,0.5) 64(-4.837,0) 65(-4.837,-0.5) 66(-4.837,-1) 67(-4.837,-1.5) 68(-4.837,-2) 69(-4.837,-2.5) 70(-4.837,-3) 71(-4.837,-3.5) 72(-4.837,-4)
  rect 5.994x5.994 smd: PAD(0,0.25)
SOT223-2
  rect 1.143x1.93 smd: 1(-2.286,-3.023) 2(0,-3.023) 3(2.286,-3.023)
  rect 2.997x1.93 smd: 4(0,3.023)
SWB3S1000
  rect 1.524x1.27 smd: 1(3.937,-2.286) 2(-3.937,-2.286) 3(3.937,2.286) 4(-3.937,2.286)
TSSOP14
  rect 0.432x1.778 smd: 1(-1.95,-2.92) 2(-1.3,-2.92) 3(-0.65,-2.92) 4(0,-2.92) 5(0.65,-2.92) 6(1.3,-2.92) 7(1.95,-2.92) 8(1.95,2.92) 9(1.3,2.92) 10(0.65,2.92) 11(0,2.92) 12(-0.65,2.92) 13(-1.3,2.92) 14(-1.95,2.92)
unnamed#2
  round 5.207 hole 3.937 unplated: (0,0)
US8
  rect 0.305x0.711 smd: 1(-0.75,-1.343) 2(-0.25,-1.343) 3(0.25,-1.343) 4(0.75,-1.343) 5(0.75,1.343) 6(0.25,1.343) 7(-0.25,1.343) 8(-0.75,1.343)
XTALABM3B
  rect 1.803x1.194 smd: 1(-2,-1.2) 2(2,-1.2) 3(2,1.2) 4(-2,1.2)

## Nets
AVDD5: C24.1 C31.1 C35.1 C36.1 C38.1 C40.1 C115.1 E7.2(N2) U4.18 U4.24(VPS2)
AVDD33: C39.1 C85.1 C87.1 C89.1 C90.1 C92.P C120.1 C126.1 C127.1 C128.1 E5.2(N2) TP9.1(N1) X1.55 X1.58 X1.65 X1.68 X2.55 X2.58 X2.65 X2.68
DVDD18: C43.1 C46.1 C54.1 C59.1 C68.1 C69.1 C72.1 C73.1 C76.1 C77.1 C83.1 C86.1 C106.1 C110.P C117.1 C121.1 C122.1 C123.1 C145.1 C149.1 C150.1 C153.1 C200.1 C202.1 E2.2(N2) R16.1 R20.2(N2) R25.1 R29.1 R39.1 R40.2(N2) TP3.1(N1) X1.7 X1.12 X1.19 X1.36 X1.43 X1.48 X1.49 X2.7 X2.12 X2.19 X2.36 X2.43 X2.48 X2.49 XR1.1 XU1.1
APLANE: C1.N(N2) C5.2(N2) C7.2(N2) C9.2(N2) C10.2(N2) C11.2(N2) C12.2(N2) C13.2(N2) C14.2(N2) C15.2(N2) C16.2(N2) C17.2(N2) C20.2(N2) C21.2(N2) C22.1 C24.2(N2) C25.2(N2) C26.2(N2) C27.2(N2) C28.2(N2) C30.2(N2) C31.2(N2) C33.2(N2) C34.2(N2) C35.2(N2) C36.2(N2) C37.2(N2) C38.2(N2) C39.2(N2) C40.2(N2) C42.2(N2) C43.2(N2) C46.2(N2) C49.1 C50.2(N2) C51.N(N2) C52.N(N2) C53.2(N2) C54.2(N2) C55.N(N2) C56.N(N2) C57.2(N2) C58.2(N2) C59.2(N2) C60.2(N2) C61.2(N2) C62.2(N2) C63.2(N2) C64.2(N2) C65.2(N2) C66.2(N2) C67.2(N2) C68.2(N2) C69.2(N2) C70.2(N2) C71.2(N2) C72.2(N2) C73.2(N2) C74.1 C75.1 C76.2(N2) C77.2(N2) C78.2(N2) C79.2(N2) C80.2(N2) C81.1 C82.1 C83.2(N2) C84.2(N2) C85.2(N2) C86.2(N2) C87.2(N2) C88.2(N2) C89.2(N2) C90.2(N2) C91.2(N2) C92.N(N2) C94.2(N2) C96.2(N2) C99.1 C101.2(N2) C105.2(N2) C106.2(N2) C110.N(N2) C111.2(N2) C112.N(N2) C113.2(N2) C114.N(N2) C115.2(N2) C116.N(N2) C117.2(N2) C118.2(N2) C120.2(N2) C121.2(N2) C122.2(N2) C123.2(N2) C126.2(N2) C127.2(N2) C128.2(N2) C137.2(N2) C139.2(N2) C140.2(N2) C142.2(N2) C144.2(N2) C145.2(N2) C147.N(N2) C148.2(N2) C149.2(N2) C150.2(N2) C153.2(N2) C154.2(N2) C200.2(N2) C202.2(N2) CR3.C DS1.C DS2.C J1.2 J1.3 J1.4 J1.5(SH4) J2.2 J2.3 J2.4 J2.5(SH4) J3.2 J3.3 J3.4 J3.5(SH4) J4.2 J4.3 J4.4 J4.5(SH4) J6.2 J6.3(SH2) J15.2 J15.3(SH2) P1.BG1 P1.BG2 P1.BG3 P1.BG4 P1.BG5 P1.BG6 P1.BG7 P1.BG8 P1.BG9 P1.BG10 P1.DG1 P1.DG2 P1.DG3 P1.DG4 P1.DG5 P1.DG6 P1.DG7 P1.DG8 P1.DG9(N9) P1.DG10 P2.BG1 P2.BG2 P2.BG3 P2.BG4 P2.BG5 P2.BG6 P2.BG7 P2.BG8 P2.BG9 P2.BG10 P2.DG1 P2.DG2 P2.DG3 P2.DG4 P2.DG5 P2.DG6 P2.DG7 P2.DG8 P2.DG9(N9) P2.DG10 P6.1 P6.2(N2) R3.2(N2) R4.2(N2) R5.2(N2) R7.2(N2) R9.2(N2) R11.1 R12.1 R18.2(N2) R19.2(N2) R21.2(N2) R23.2(N2) R27.2(N2) R28.2(N2) R32.2(N2) R33.2(N2) R42.2(N2) R44.2(N2) S1.1 S1.2 S2.3(N5) S2.4 S3.3(N5) S3.4 T2.4 T3.1 T3.5 T7.3 T7.5 TP2.1(N1) TP4.1(N1) TP10.1(N1) TP12.1(N1) TP19.1(N1) U1.37 U1.44 U1.59 U1.PAD U3.13 U3.PAD U4.2 U4.5 U4.8 U4.11 U4.12 U4.14 U4.17 U4.19 U4.20 U4.23 U4.PAD U6.1 U7.1 U10.1 U11.1 U15.4 X1.PAD X2.PAD XC1.2(N2) XC2.2(N2) XC3.2(N2) XC4.N(N2) XC5.2(N2) XC6.2(N2) XC7.2(N2) XC8.2(N2) XD1.C XP1.6(N6) XP2.5(N5) XP2.PAD1 XP2.PAD2 XP2.PAD3 XP2.PAD4 XU1.7 XU2.6 XU2.30 XU2.31 XU2.PAD XU3.7 XY1.2 XY1.4
CVDD18: C5.1 C28.1 C50.1 C53.1 C60.1 C71.1 C78.1 C84.1 C88.1 C94.1 C137.1 C139.1 C140.1 C142.1 C144.1 C147.P C148.1 C154.1 E1.2(N2) TP1.1(N1) X1.1 X1.4 X1.59 X1.60 X1.63 X1.64 X1.71 X1.72 X2.1 X2.4 X2.59 X2.60 X2.63 X2.64 X2.71 X2.72
D0_N: P2.B8 X1.47
D0_P: P2.A8 X1.46
D1_N: P2.B7 X1.45
D1_P: P2.A7 X1.44
D2_0_N: P2.D8 X2.47
D2_0_P: P2.C8 X2.46
D2_1_N: P2.D7 X2.45
D2_1_P: P2.C7 X2.44
D2_2_N: P2.D6 X2.42
D2_2_P: P2.C6 X2.41
D2_3_N: P2.D5 X2.40
D2_3_P: P2.C5 X2.39
D2_4_N: P2.D4 X2.38
D2_4_P: P2.C4 X2.37
D2_5_N: P2.D3 X2.35
D2_5_P: P2.C3 X2.34
D2_6_N: P2.D2 X2.33
D2_6_P: P2.C2 X2.32
D2_7_N: P2.D1 X2.31
D2_7_P: P2.C1 X2.30
D2_8_N: P1.D10 X2.27
D2_8_P: P1.C10 X2.26
D2_9_N: P1.D9 X2.25
D2_9_P: P1.C9 X2.24
D2_10_N: P1.D8 X2.23
D2_10_P: P1.C8 X2.22
D2_11_N: P1.D7 X2.21
D2_11_P: P1.C7 X2.20
D2_12_N: P1.D6 X2.18
D2_12_P: P1.C6 X2.17
D2_13_N: P1.D5 X2.16
D2_13_P: P1.C5 X2.15
D2_14_N: P1.D4 X2.14
D2_14_P: P1.C4 X2.13
D2_15_N: P1.D3 X2.11
D2_15_P: P1.C3 X2.10
D2_N: P2.B6 X1.42
D2_P: P2.A6 X1.41
D3_N: P2.B5 X1.40
D3_P: P2.A5 X1.39
D4_N: P2.B4 X1.38
D4_P: P2.A4 X1.37
D5_N: P2.B3 X1.35
D5_P: P2.A3 X1.34
D6_N: P2.B2 X1.33
D6_P: P2.A2 X1.32
D7_N: P2.B1 X1.31
D7_P: P2.A1 X1.30
D8_N: P1.B10 X1.27
D8_P: P1.A10 X1.26
D9_N: P1.B9 X1.25
D9_P: P1.A9 X1.24
D10_N: P1.B8 X1.23
D10_P: P1.A8 X1.22
D11_N: P1.B7 X1.21
D11_P: P1.A7 X1.20
D12_N: P1.B6 X1.18
D12_P: P1.A6 X1.17
D13_N: P1.B5 X1.16
D13_P: P1.A5 X1.15
D14_N: P1.B4 X1.14
D14_P: P1.A4 X1.13
D15_N: P1.B3 X1.11
D15_P: P1.A3 X1.10
DACCK2_N: C119.1 R28.1 U1.28
DACCK2_P: C109.1 R27.1 U1.29
DACCK_N: C133.1 R42.1 U1.25
DACCK_P: C93.1 R7.1 U1.26
DCI1_N: P1.B2 X1.29
DCI1_P: P1.A2 X1.28
DCI2_N: P2.D9 X2.29
DCI2_P: P2.C9 X2.28
DCO_N: U1.45 U3.9
DCO_P: U1.46 U3.12
FILT_1_N: C23.2(N2) C80.1 JP5.3 L11.1
FILT_1_P: C23.1 C81.2(N2) JP4.3 L10.1
FILT_2_N: C74.2(N2) C97.1 JP7.3 L8.1
FILT_2_P: C65.1 C97.2(N2) JP6.3 L9.1
FRAME1_N: U1.34 X1.9
FRAME1_P: U1.33 X1.8
FRAME2_N: U1.36 X2.9
FRAME2_P: U1.35 X2.8
IBB_N: C44.2(N2) C96.1 L6.2(N2) R200.2(N2) U4.22
IBB_P: C44.1 C49.2(N2) L5.2(N2) R200.1 U4.21
INTB: CR5.C X1.51 XU2.21
INTB2: CR6.C X1.50 XU2.22
INTB2_2: DS4.C X2.50 XU2.24
INTB_2: DS3.C X2.51 XU2.23
INTERNAL_MOSI: R26.1 XU1.12 XU2.1 XU3.12
INTERNAL_SCK: XU1.13 XU2.10 XU3.13
MISO2: U1.21 XU3.4
MOSI1: X1.52 X2.52 XU1.3
MOSI2: U1.22 XU3.3
Q1_N: P1.B1 U3.2
Q1_P: P1.A1 U3.1
Q2_N: P2.D10 U3.4
Q2_P: P2.C10 U3.3
QBB_N: C99.2(N2) C100.1 L7.2(N2) R202.1 U4.9
QBB_P: C100.2(N2) C101.1 L13.2(N2) R202.2(N2) U4.10
REFCK2_N: C108.1 R32.1 U1.52
REFCK2_P: C104.1 R33.1 U1.53
REFCK_N: C107.1 R23.1 U1.55
REFCK_P: C103.1 R44.1 U1.56
SCK1: X1.53 X2.53 XU1.2
SCK2: U1.16 XU3.2
SSEL1: X1.54 XU1.5
SSEL2: U1.17 XU3.5
SSEL3: X2.54 XU1.4
UNNAMED_1_ADL5375_I71_LOIN: C22.2(N2) U4.4
UNNAMED_1_ADL5375_I71_LOIP: C8.2(N2) U4.3
UNNAMED_1_ADL5375_I71_RFOUT: C32.1 U4.16
UNNAMED_1_CAP_I74_N1: C8.1 J15.1
UNNAMED_1_CAP_I75_N2: C32.2(N2) J6.1
UNNAMED_1_CAP_I93_N1: C64.1 C98.2(N2) L9.2(N2) L13.1
UNNAMED_1_CAP_I96_N1: C75.2(N2) C98.1 L7.1 L8.2(N2)
UNNAMED_1_CAP_I110_N1: C48.2(N2) C79.1 L6.1 L11.2(N2)
UNNAMED_1_CAP_I116_N1: C48.1 C82.2(N2) L5.1 L10.2(N2)
UNNAMED_2_ADG3304_I104_EN: XR1.2(N2) XU1.8
UNNAMED_2_ADG3304_I104_Y3: XU1.11 XU2.40
UNNAMED_2_ADG3304_I104_Y4: XU1.10(Y4) XU2.38
UNNAMED_2_ADG3304_I105_EN: XR5.2(N2) XU3.8
UNNAMED_2_ADG3304_I105_Y3: R26.2(N2) XU2.9 XU3.11
UNNAMED_2_ADG3304_I105_Y4: XU2.39 XU3.10(Y4)
UNNAMED_2_CAP_I4_N1: XC1.1 XR3.1 XU2.32 XY1.1
UNNAMED_2_CAP_I5_N1: XC2.1 XR3.2(N2) XU2.33 XY1.3(N2)
UNNAMED_2_CAP_I110_N1: XC3.1 XU2.37(VUSB)
UNNAMED_2_CN6P_I38_N1: XP1.1 XU2.17
UNNAMED_2_CN6P_I38_N3: XP1.3 XU2.16
UNNAMED_2_CN6P_I38_N4: XP1.4 XU2.15
UNNAMED_2_CN6P_I38_N5: XP1.5 XR2.2(N2) XU2.18
UNNAMED_2_DIOLED_I84_P: XD1.A(P) XR4.2(N2)
UNNAMED_2_ICPIC18F4550_I2_RC2CC: XR4.1 XU2.36
UNNAMED_4_ADP3338_I421_IN: C1.P C33.1 C34.1 C37.1 C105.1 JP23.1 P5.1 P5.2(N2) U6.3 U7.3 U10.3 U11.3
UNNAMED_4_ADP3338_I421_OUT1: C27.1 JP2.1 U6.2
UNNAMED_4_ADP3338_I428_OUT1: C63.1 JP9.1 U10.2
UNNAMED_4_ADP3338_I429_OUT1: C111.1 JP11.1 U11.2
UNNAMED_4_ADP3338_I441_OUT1: C30.1 JP3.1 U7.2
UNNAMED_4_CAP_I24_N1: C51.P C57.1 E1.1 JP2.2(S2)
UNNAMED_4_CAP_I39_N1: C52.P C58.1 E2.1 JP3.2(S2)
UNNAMED_4_CAP_I133_N1: C55.P C61.1 E5.1 JP9.2(S2)
UNNAMED_4_CAP_I150_N1: C56.P C62.1 E6.1 JP11.2(S2)
UNNAMED_4_CAP_I406_N1: C112.P C113.1 E7.1 JP23.2(S2) TP18.1(N1)
UNNAMED_8_CAP_I44_N2: C104.2(N2) R43.2(N2) X2.2
UNNAMED_8_CAP_I45_N2: C108.2(N2) R43.1 X2.3
UNNAMED_8_CAP_I48_N2: C109.2(N2) R41.1 X2.62
UNNAMED_8_CAP_I58_N1: C116.P C118.1 TP20.1(N1) X2.70
UNNAMED_8_CAP_I67_N2: C119.2(N2) R41.2(N2) X2.61
UNNAMED_8_CNBNC5P_I79_CNTR: J4.1 T3.3
UNNAMED_8_DIOLED_I62_P: DS4.A(P) R29.2(N2)
UNNAMED_8_DIOLED_I63_P: DS3.A(P) R25.2(N2)
UNNAMED_8_NC3PJMPR_I72_A: JP7.1 T1.1
UNNAMED_8_NC3PJMPR_I72_COM: JP7.2(COM) R5.1 X2.67
UNNAMED_8_NC3PJMPR_I73_A: JP6.1 T1.3
UNNAMED_8_NC3PJMPR_I73_COM: JP6.2(COM) R18.1 X2.66
UNNAMED_8_RES_I59_N1: R3.1 X2.69
UNNAMED_8_RES_I82_N1: R20.1 X2.6
UNNAMED_8_SKTQFN72PAD_I56_N5: S3.1 S3.2 X2.5
UNNAMED_8_XFMRETC1_I74_N3: T1.4 T3.4(SECP)
UNNAMED_8_XFMRETC1_I74_N4: T1.5(N4) T3.6
UNNAMED_11_AD9516_I1_BYPASS: C2.2(N2) C3.2(N2) C4.2(N2) C26.1 U1.10
UNNAMED_11_AD9516_I1_CLK_1: C18.2(N2) U1.13
UNNAMED_11_AD9516_I1_CLKN: C19.2(N2) U1.14
UNNAMED_11_AD9516_I1_CP: C4.1 R1.2(N2) R2.1 U1.5
UNNAMED_11_AD9516_I1_CPRSET: R12.2(N2) U1.62
UNNAMED_11_AD9516_I1_LD: TP14.1(N1) U1.3 U15.3
UNNAMED_11_AD9516_I1_LF: C2.1 R1.1 U1.9
UNNAMED_11_AD9516_I1_REFIN1: C29.2(N2) U1.64
UNNAMED_11_AD9516_I1_REFMON: TP15.1(N1) U1.2 U15.1
UNNAMED_11_AD9516_I1_RESETN: S1.3(N5) S1.4 U1.23
UNNAMED_11_AD9516_I1_RSET: R11.2(N2) U1.58
UNNAMED_11_AD9516_I1_STATUS: TP13.1(N1) U1.6 U15.6
UNNAMED_11_CAP_I46_N1: C29.1 J2.1 R9.1
UNNAMED_11_CAP_I224_N1: C18.1 CR4.3 R6.1 T2.1(SEC_DOT)
UNNAMED_11_CAP_I226_N1: C19.1 CR4.1(P) CR4.2 R6.2(N2) T2.3
UNNAMED_11_CAP_I235_N1: C3.1 R2.2(N2)
UNNAMED_11_CNBNC5P_I230_CNTR: J1.1 T2.5
UNNAMED_11_DIOLED_I108_P: CR3.A(P) R14.2(N2)
UNNAMED_11_DIOLED_I260_P: DS2.A(P) R13.2(N2)
UNNAMED_11_DIOLED_I261_P: DS1.A(P) R10.2(N2)
UNNAMED_11_RES_I113_N1: R14.1 U15.7
UNNAMED_11_RES_I114_N1: R13.1 U15.5
UNNAMED_11_RES_I115_N1: R10.1 U15.2
UNNAMED_12_CAP_I386_N1: C91.1 C114.P TP16.1(N1) X1.70
UNNAMED_12_CAP_I532_N2: C103.2(N2) R22.2(N2) X1.2
UNNAMED_12_CAP_I533_N2: C107.2(N2) R22.1 X1.3
UNNAMED_12_CAP_I534_N2: C93.2(N2) R38.1 X1.62
UNNAMED_12_CAP_I535_N2: C133.2(N2) R38.2(N2) X1.61
UNNAMED_12_CNBNC5P_I550_CNTR: J3.1 T7.1
UNNAMED_12_DIOLED_I528_P: CR5.A(P) R16.2(N2)
UNNAMED_12_DIOLED_I529_P: CR6.A(P) R39.2(N2)
UNNAMED_12_NC3PJMPR_I562_A: JP5.1 T5.3
UNNAMED_12_NC3PJMPR_I562_COM: JP5.2(COM) R19.1 X1.66
UNNAMED_12_NC3PJMPR_I563_A: JP4.1 T5.1
UNNAMED_12_NC3PJMPR_I563_COM: JP4.2(COM) R4.1 X1.67
UNNAMED_12_RES_I387_N1: R21.1 X1.69
UNNAMED_12_RES_I574_N1: R40.1 X1.6
UNNAMED_12_SKTQFN72PAD_I319_N5: S2.1 S2.2 X1.5
UNNAMED_12_XFMRETC1_I551_N3: T5.4 T7.4(SECP)
UNNAMED_12_XFMRETC1_I551_N4: T5.5(N4) T7.6
UNNAMED_13_ICSY89833_I43_Q0: R31.1 U3.15
UNNAMED_13_ICSY89833_I43_Q0N: R31.2(N2) U3.16
UNNAMED_13_ICSY89833_I43_Q3: R30.2(N2) U3.5
UNNAMED_13_ICSY89833_I43_Q3N: R30.1 U3.6
USB_D+: XP2.3 XU2.43
USB_D-: XP2.2 XU2.42
USB_VCC: XC4.P XC5.1 XC6.1 XC7.1 XC8.1 XP1.2 XP2.1 XR2.1 XU1.14 XU2.7 XU2.8 XU2.28 XU2.29 XU3.14
XCVDD33: C7.1 C9.1 C10.1 C11.1 C12.1 C13.1 C14.1 C15.1 C16.1 C17.1 C20.1 C21.1 C25.1 C42.1 C66.1 C67.1 C70.1 E6.2(N2) TP11.1(N1) U1.1 U1.4 U1.11 U1.12 U1.27 U1.30 U1.31 U1.32 U1.38 U1.41 U1.49 U1.50 U1.51 U1.54(VS_LVPECL3) U1.57 U1.60 U1.61 U3.7 U3.14 U15.8(VCC) XR5.1 XU3.1

Pads without a net: P1 C1 C2 D1 D2; P2 A9 A10 B9 B10; T1 2; T2 2; T3 2; T5 2; T7 2; U1 7 8 15 18 19 20 24 39 40 42 43 47 48 63; U3 8 10 11; U4 1 6 7 13 15; U6 4; U7 4; U10 4; U11 4; X1 56 57; X2 56 57; XP2 4; XU1 6 9; XU2 2 3 4 5 11 12 13 14 19 20 25 26 27 34 35 41 44; XU3 6 9

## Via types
v1: diameter 0.762, hole 0.406, TOP to BOTTOM, 627 vias
v2: diameter 0.508, hole 0.254, TOP to BOTTOM, 171 vias
v3: diameter 0.711, hole 0.381, TOP to BOTTOM, 183 vias
v4: diameter 0.66, hole 0.406, TOP to BOTTOM, 16 vias

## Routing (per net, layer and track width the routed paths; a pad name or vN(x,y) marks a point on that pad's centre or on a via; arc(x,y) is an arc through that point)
AVDD5: length 7.7
  TOP w0.254: U4.24 88.79,88.88 88.39,89.28 v1(88.01,89.28) ; v1(92.32,88.65) 92.04,88.37 U4.18
  TOP w0.508: E7.2 84.45,124.21 v1(84.45,124.46) ; C40.1 87.5,89.79 v1(88.01,89.28)
  TOP w0.635: C36.1 v1(87.5,92.33) ; C35.1 v1(93.47,91.31) ; C24.1 v1(93.6,93.22) ; C38.1 v1(93.47,89.79) ; C31.1 v1(87.5,93.85)
  vias: v1(82.55,127.25) v1(82.55,125.86) v1(82.55,124.46) v1(82.55,123.06) v1(84.45,128.65) v1(84.45,127.25) v1(84.45,125.86) v1(84.45,123.06)
AVDD33: length 29.2
  TOP w0.254: X1.58 54.49,113.31 v2(54.64,113.16) ; X2.58 54.31,51.71 54.39,51.79 v2(54.48,51.79) ; X2.55 54.79,50.21 54.97,50.03 v3(54.99,50.03) ; v3(54.69,54.96) 54.67,54.96 54.42,55.21 X2.65 ; v3(54.69,116.55) 54.67,116.55 54.42,116.81 X1.65 ; X2.68 v3(54.7,56.71) ; v3(54.74,111.73) 54.67,111.81 X1.55 ; X1.68 v3(54.7,118.31)
  TOP w0.381: 73.79,155.78 TP9.1 ; TP9.1 74.98,156.97 ; TP9.1 73.79,158.17 ; TP9.1 72.59,156.97
  TOP w0.508: v1(74.42,160.53) 74.17,160.78 74.17,161.48 E5.2 ; v1(72.14,116.71) C92.P v3(73.79,115.32)
  L5_PWR w0.254: TP9.1 74.98,156.97 ; TP9.1 73.79,155.78 ; TP9.1 73.79,158.17 ; TP9.1 72.59,156.97
  BOTTOM w0.508: C90.1 55.25,112.88 54.97,113.16 v2(54.64,113.16) ; v3(54.7,118.31) 54.74,118.34 C89.1 ; v3(54.69,54.96) 54.69,54.97 54.74,54.97 54.99,55.22 55.37,55.22 C127.1 ; v3(54.99,50.03) 55.1,50.14 C120.1 ; v3(54.7,56.71) 54.74,56.74 C128.1 ; C85.1 v3(54.74,111.73) ; v2(54.48,51.79) 54.64,51.79 54.76,51.67 54.86,51.67 55.25,51.28 C126.1 ; C87.1 55.37,116.81 54.99,116.81 54.74,116.56 54.69,116.56 v3(54.69,116.55)
  vias: v1(73.03,160.4) v1(73.03,159.38) v1(74.42,159.38) v1(75.82,160.53) v1(75.82,159.38)
DVDD18: length 47.4
  TOP w0.203: v3(50.29,110.34) 50.55,110.59 50.55,110.85 50.65,110.94 X1.49
  TOP w0.254: X2.19 43.37,58.71 v3(43.31,58.78) ; v3(50.34,119.86) 50.29,119.91 50.29,120.12 50.14,120.26 X1.7 ; v3(50.29,110.34) 50.14,110.48 X1.48 ; X1.36 44.01,111.81 v3(43.69,111.48) ; X2.7 50.14,58.67 50.29,58.52 50.29,58.32 v3(50.34,58.27) ; v3(43.69,49.89) 44.01,50.21 X2.36
  TOP w0.279: v3(47.12,58.27) 47.65,58.8 X2.12 ; v3(47.12,119.86) 47.65,120.39 X1.12 ; v3(47.62,112.12) 47.62,111.24 X1.43 ; v3(47.62,50.52) 47.62,49.64 X2.43
  TOP w0.305: X2.48 50.14,49.04 v3(50.42,48.77) 50.65,48.99 X2.49 ; v3(43.05,120.52) 43.18,120.52 43.4,120.31 X1.19
  TOP w0.381: TP3.1 13.46,158.42 ; TP3.1 12.27,157.23 ; TP3.1 14.66,157.23 ; TP3.1 13.46,156.03 ; XU1.1 59.1,35.48 v1(59.44,35.81)
  TOP w0.508: v1(14.99,160.66) 14.99,160.84 E2.2 13.34,161.22 13.34,160.91 v1(13.59,160.66) ; XR1.1 v1(53.94,30.19) ; R25.1 v3(43.69,40.36) ; v3(43.56,102.49) 44.2,101.85 R16.1 ; R20.2 v3(49.7,65.62) ; R39.1 v3(43.71,103.99) ; v3(11.94,142.37) C110.P v3(10.26,140.94) ; R29.1 v3(43.69,42.52) ; R40.2 v3(49.72,127.06)
  L6_PWR w0.254: TP3.1 13.46,158.42 ; TP3.1 12.27,157.23 ; TP3.1 14.66,157.23 ; TP3.1 13.46,156.03
  BOTTOM w0.508: v3(49.15,112.24) C121.1 ; C200.1 v3(50.55,50.77) ; C54.1 v3(43.69,49.89) ; v3(42.67,111.73) 43.18,112.24 C106.1 ; C86.1 43.18,50.65 v3(42.67,50.14) ; v3(43.31,58.78) 43.43,58.78 C76.1 ; C202.1 50.55,58.27 v3(50.34,58.27) ; v3(43.05,120.52) 43.59,119.99 C123.1 44.2,120.37 C122.1 v2(44.2,121.92) ; v3(47.12,58.27) C83.1 ; C145.1 v3(50.55,112.37) ; v3(49.15,50.65) C59.1 ; v3(50.34,119.86) 50.55,119.86 C72.1 ; v3(46.61,112.24) C150.1 ; v3(46.61,50.65) C68.1 ; v3(47.12,119.86) C77.1 ; C117.1 v3(43.69,111.48)
  vias: v1(10.67,160.66) v1(10.67,159.13) v1(12.06,160.66) v1(12.06,159.13) v1(13.59,159.13) v1(14.99,159.13) v1(16.13,160.66) v1(16.13,159.13) v3(43.94,59.66) v3(48.26,119.86) v3(48.26,58.27)
